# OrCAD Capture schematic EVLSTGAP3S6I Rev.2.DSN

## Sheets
1 Gate Driver: size A3; rev: R2; note: <Doc>
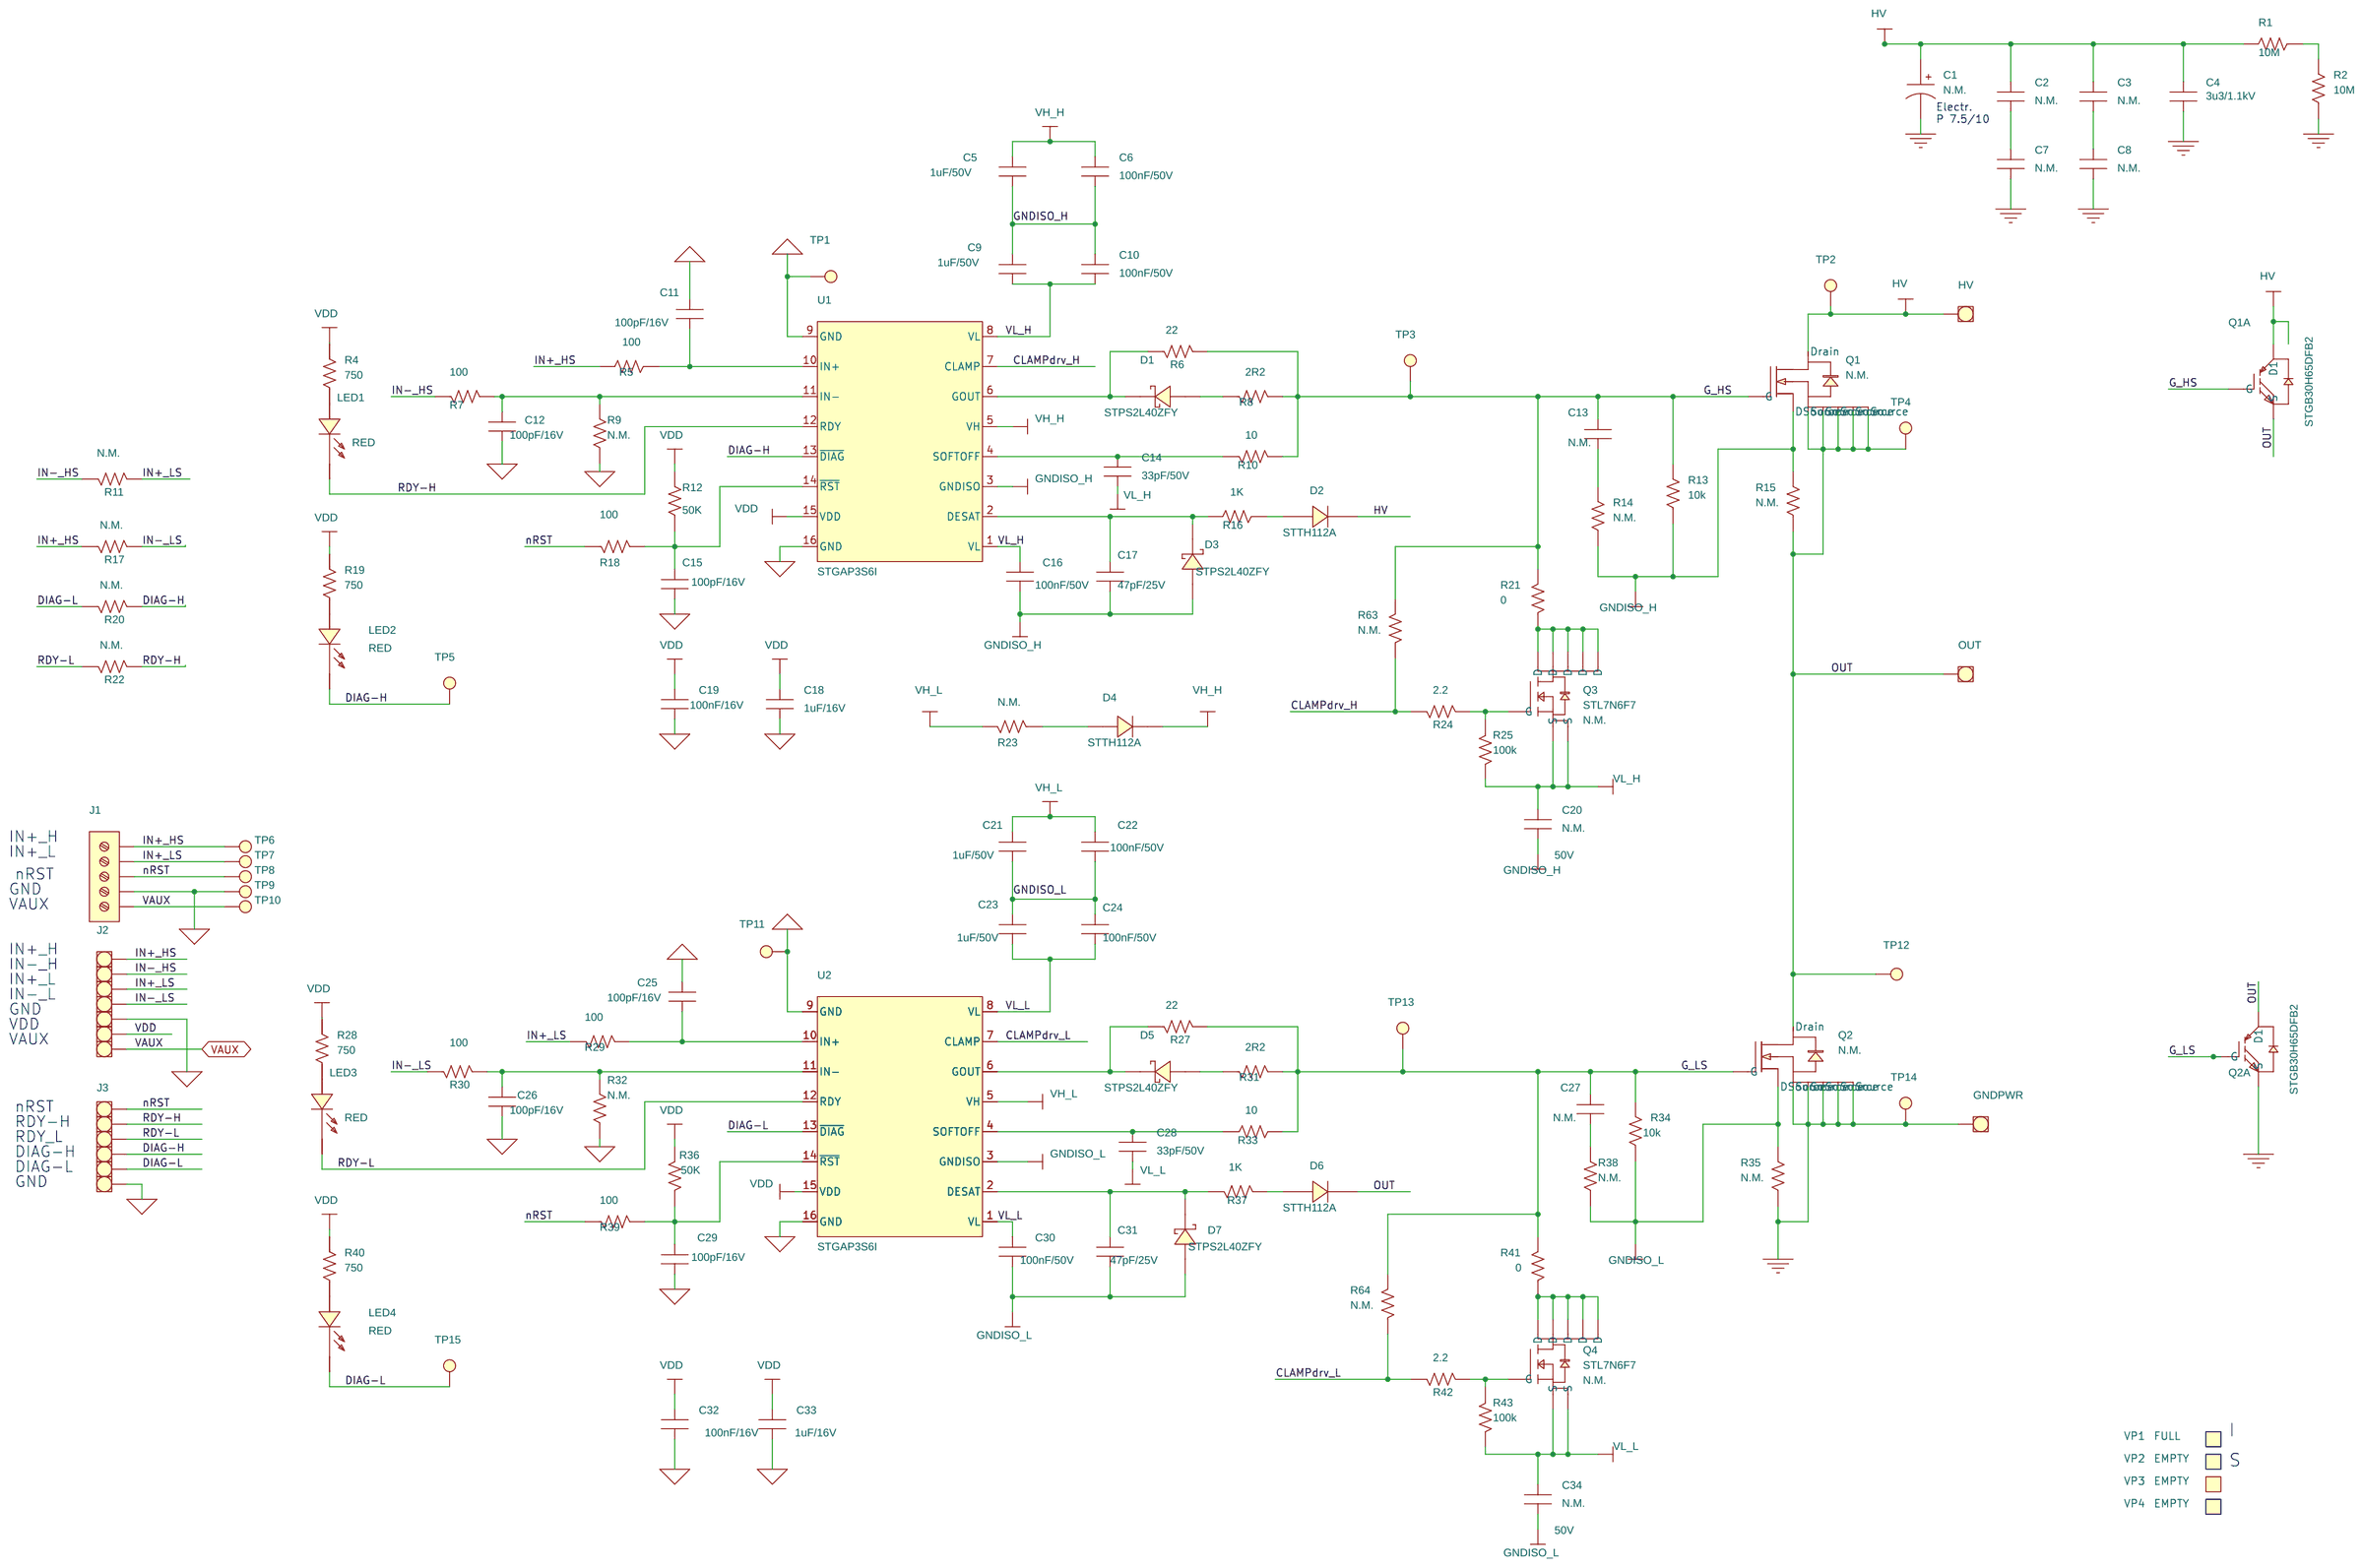
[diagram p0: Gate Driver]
2 Supply: size A4
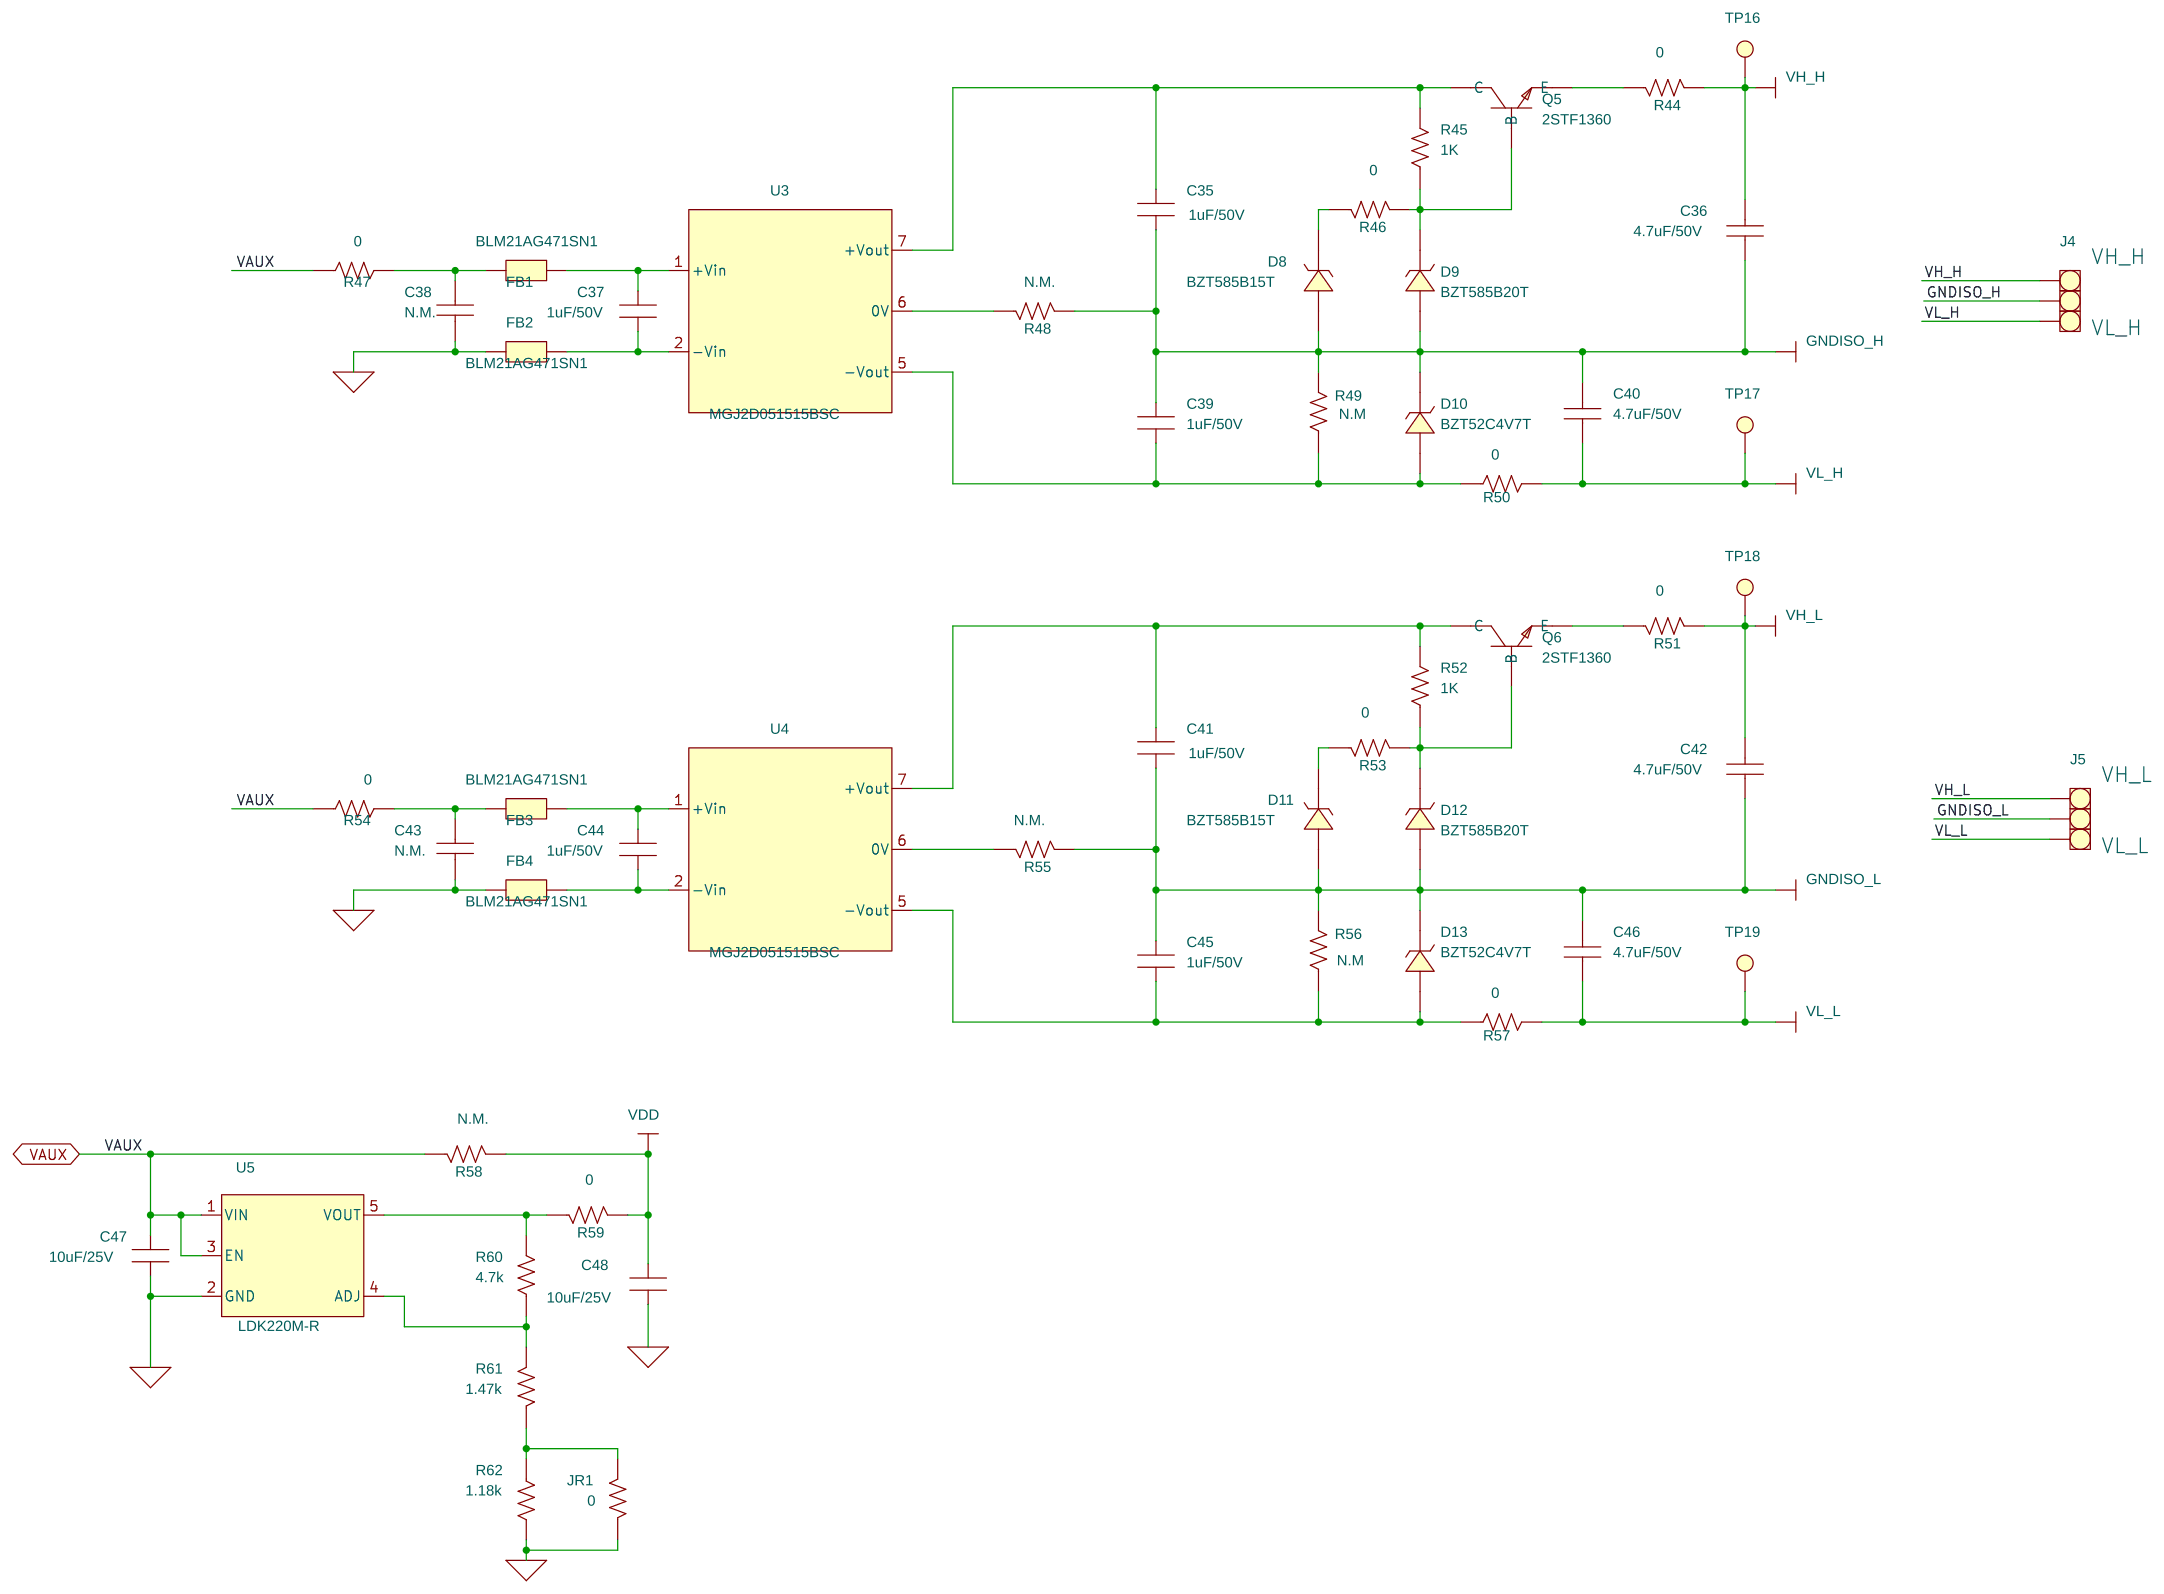
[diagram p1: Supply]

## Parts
sheet Gate Driver
C1  N.M.  [CAPE-R22H50-P100]
C2  N.M.  [C2225]
C3  N.M.  [C2225]
C4  3u3/1.1kV  [CAP-RAD-16X31_5H29_5P27_5]
C5  1uF/50V  [C0603]
C6  100nF/50V  [C0603]
C7  N.M.  [C2225]
C8  N.M.  [C2225]
C9  1uF/50V  [C0603]
C10  100nF/50V  [C0603]
C11  100pF/16V  [C0603]
C12  100pF/16V  [C0603]
C13  N.M.  [C0603]
C14  33pF/50V  [C0402]
C15  100pF/16V  [C0603]
C16  100nF/50V  [C0603]
C17  47pF/25V  [C0603]
C18  1uF/16V  [C0603]
C19  100nF/16V  [C0603]
C20  N.M.  [C0603]
C21  1uF/50V  [C0603]
C22  100nF/50V  [C0603]
C23  1uF/50V  [C0603]
C24  100nF/50V  [C0603]
C25  100pF/16V  [C0603]
C26  100pF/16V  [C0603]
C27  N.M.  [C0603]
C28  33pF/50V  [C0402]
C29  100pF/16V  [C0603]
C30  100nF/50V  [C0603]
C31  47pF/25V  [C0603]
C32  100nF/16V  [C0603]
C33  1uF/16V  [C0603]
C34  N.M.  [C0603]
D1  STPS2L40ZFY  [SOD-123]
D2  STTH112A  [DO-214AC]
D3  STPS2L40ZFY  [SOD-123]
D4  STTH112A  [DO-214AC]
D5  STPS2L40ZFY  [SOD-123]
D6  STTH112A  [DO-214AC]
D7  STPS2L40ZFY  [SOD-123]
GNDPWR  PAD_4_7D2_4MM  [PAD-10F3_2]
HV  PAD_4_7D2_4MM  [PAD-10F3_2]
J1  MORSV-350-5P_screw  [MORS_WR-TBL_691243110005_5P_3V5]
J2  STRIP 1x7  [STRIP_7V]
J3  STRIP 1x6  [STRIP_6V]
LED1  RED  [led-0805]
LED2  RED  [led-0805]
LED3  RED  [led-0805]
LED4  RED  [led-0805]
OUT  PAD_4_7D2_4MM  [PAD-10F3_2]
Q1  N.M.  [H2PAK-7]
Q1A  STGB30H65DFB2  [D2PAK]
Q2  N.M.  [H2PAK-7]
Q2A  STGB30H65DFB2  [D2PAK]
Q3  STL7N6F7  [POWERFLAT6-2X2_P065-E]
Q4  STL7N6F7  [POWERFLAT6-2X2_P065-E]
R1  10M  [R1206]
R2  10M  [R1206]
R4  750  [R0603]
R5  100  [R0603]
R6  22  [R1210]
R7  100  [R0603]
R8  2R2  [R1210]
R9  N.M.  [R0603]
R10  10  [R0805]
R11  N.M.  [R0402]
R12  50K  [R0603]
R13  10k  [R0402]
R14  N.M.  [R0402]
R15  N.M.  [R0402]
R16  1K  [R0603]
R17  N.M.  [R0402]
R18  100  [R0603]
R19  750  [R0603]
R20  N.M.  [R0402]
R21  0  [R0402]
R22  N.M.  [R0402]
R23  N.M.  [R0805]
R24  2.2  [R0402]
R25  100k  [R0402]
R27  22  [R1210]
R28  750  [R0603]
R29  100  [R0603]
R30  100  [R0603]
R31  2R2  [R1210]
R32  N.M.  [R0603]
R33  10  [R0805]
R34  10k  [R0402]
R35  N.M.  [R0402]
R36  50K  [R0603]
R37  1K  [R0603]
R38  N.M.  [R0402]
R39  100  [R0603]
R40  750  [R0603]
R41  0  [R0402]
R42  2.2  [R0402]
R43  100k  [R0402]
R63  N.M.  [R0402]
R64  N.M.  [R0402]
TP1  TP-diam1_27mm-Hole0_8mm  [TP-F0_8_PAD_1_35]
TP2  TP-diam1_27mm-Hole0_8mm  [TP-F0_8_PAD_1_35]
TP3  TP-diam1_27mm-Hole0_8mm  [TP-F0_8_PAD_1_35]
TP4  TP-diam1_27mm-Hole0_8mm  [TP-F0_8_PAD_1_35]
TP5  TP-diam1_27mm-Hole0_8mm  [TP-F0_8_PAD_1_35]
TP6  TP-diam1_27mm-Hole0_8mm  [TP-1_5]
TP7  TP-diam1_27mm-Hole0_8mm  [TP-1_5]
TP8  TP-diam1_27mm-Hole0_8mm  [TP-1_5]
TP9  TP-diam1_27mm-Hole0_8mm  [TP-1_5]
TP10  TP-diam1_27mm-Hole0_8mm  [TP-1_5]
TP11  TP-diam1_27mm-Hole0_8mm  [TP-F0_8_PAD_1_35]
TP12  TP-diam1_27mm-Hole0_8mm  [TP-F0_8_PAD_1_35]
TP13  TP-diam1_27mm-Hole0_8mm  [TP-F0_8_PAD_1_35]
TP14  TP-diam1_27mm-Hole0_8mm  [TP-F0_8_PAD_1_35]
TP15  TP-diam1_27mm-Hole0_8mm  [TP-F0_8_PAD_1_35]
U1  STGAP3S6I  [SO16_L10_4]
U2  STGAP3S6I  [SO16_L10_4]
VP1  FULL  [square2x2mm]
VP2  EMPTY  [square2x2mm]
VP3  EMPTY  [square2x2mm]
VP4  EMPTY  [square2x2mm]
sheet Supply
C35  1uF/50V  [C0603]
C36  4.7uF/50V  [C1206]
C37  1uF/50V  [C0603]
C38  N.M.  [C0603]
C39  1uF/50V  [C0603]
C40  4.7uF/50V  [C1206]
C41  1uF/50V  [C0603]
C42  4.7uF/50V  [C1206]
C43  N.M.  [C0603]
C44  1uF/50V  [C0603]
C45  1uF/50V  [C0603]
C46  4.7uF/50V  [C1206]
C47  10uF/25V  [C0805]
C48  10uF/25V  [C0805]
D8  BZT585B15T  [SOD-523]
D9  BZT585B20T  [SOD-523]
D10  BZT52C4V7T  [SOD-523]
D11  BZT585B15T  [SOD-523]
D12  BZT585B20T  [SOD-523]
D13  BZT52C4V7T  [SOD-523]
FB1  BLM21AG471SN1  [R0805]
FB2  BLM21AG471SN1  [R0805]
FB3  BLM21AG471SN1  [R0805]
FB4  BLM21AG471SN1  [R0805]
J4  STRIP 1x3  [STRIP_3V]
J5  STRIP 1x3  [STRIP_3V]
JR1  0  [R0603]
Q5  2STF1360  [SOT-89]
Q6  2STF1360  [SOT-89]
R44  0  [R0402]
R45  1K  [R0603]
R46  0  [R0402]
R47  0  [R0603]
R48  N.M.  [R0402]
R49  N.M  [R0603]
R50  0  [R0402]
R51  0  [R0402]
R52  1K  [R0603]
R53  0  [R0402]
R54  0  [R0603]
R55  N.M.  [R0402]
R56  N.M  [R0603]
R57  0  [R0402]
R58  N.M.  [R0402]
R59  0  [R0402]
R60  4.7k  [R0603]
R61  1.47k  [R0603]
R62  1.18k  [R0603]
TP16  TP-diam1_27mm-Hole0_8mm  [TP-1_5]
TP17  TP-diam1_27mm-Hole0_8mm  [TP-1_5]
TP18  TP-diam1_27mm-Hole0_8mm  [TP-1_5]
TP19  TP-diam1_27mm-Hole0_8mm  [TP-1_5]
U3  MGJ2D051515BSC  [CONV_MGJ2]
U4  MGJ2D051515BSC  [CONV_MGJ2]
U5  LDK220M-R  [SOT23-5L]

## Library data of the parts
C1 = C_EL-DIAM10: THT Electrolitic capacitor; Package: Radial p7.5/10 d22; VOLTAGE: <VOLTAGE>
C2 C3 C7 C8 = C-2225: VOLTAGE: <VOLTAGE>
C4 = C-pitch15mm-13x18: Film capacitor; Manufacturer: Panasonic; Manufacturer Order code: ECWFG1B335J; Package: Pitch 27.5 mm; Part Number: ECWFG1B335J; VOLTAGE: <VOLTAGE>
C5 C6 C9-C13 C15-C19 C21-C27 C29-C33 = C-0603: VOLTAGE: <VOLTAGE>
C14 C28 = C-0402: VOLTAGE: <VOLTAGE>
C20 C34 = C-0603: Ifarcad Footprint: CAPC-0603; VOLTAGE: 50V
D1 D3 D5 D7 = STPS2L40ZFY_0
D2 D6 = STTH112A_1
D4 = STTH112A_1: Ifarcad Footprint: DIODO-DO214AC-SMA
GNDPWR HV OUT = PAD_4_7D2_4MM: Package: Diam. 10, hole diam. 3.2 mm
J1 = MORSV-350-5P_screw
J2 = STRIP_1x7: Strip connector 7 pos, 2.54 mm; Part Number: 68000-407HLF or Equivalent
J3 = STRIP_1x6
LED1-LED4 = LED-0805-RED-WE
Q1 Q2 = SCTH40N120G2V7AG_1: Silicon carbide Power MOSFET, 1200 V, 60 A, 35 mOhm; Part Number: SCTH60N120G2-7 or equivalent
Q1A Q2A = STGB50H65FB2_1: Trench gate field-stop, 650 V, 30 A, high-speed HB2 series IGBT; Ampere: 30 A
Q3 Q4 = STL7N6F7_0: Voltage: N.M.
R1 R2 = R-1206: SMT Resistor
R4 R5 R7 R9 R12 R16 R18 R19 R28-R30 R32 R36 R37 R39 R40 = R-0603
R6 R8 R27 R31 = R-1210
R10 R33 = R-0805
R11 R13-R15 R17 R34 R35 R38 R44 R46 R48 R50 R51 R53 R55 R57 = R-0402
R20-R22 R24 R25 R41-R43 R58 R59 R63 R64 = R-0402: Ifarcad Footprint: RESC-0402
R23 = R: SMT Resistor; Ifarcad Footprint: RESC-0805; Package: Size 0805
TP1-TP19 = TP-diam1_27mm-Hole0_8mm
U1 = STGAP3S1_6
U2 = STGAP3S1_6: Galvanically isolated 6 A single gate driver
VP1-VP4 = VERSION-POINT: PCB Assembly version solder dot
C35 C37 C39 C41 C44 C45 = C-0603: SMT Ceramic capacitor; VOLTAGE: <VOLTAGE>
C36 C40 C42 C46 = CAPACITOR_NON-POL: SMT Ceramic capacitor; Package: Size 1206
C38 C43 = CAPACITOR_NON-POL: SMT Ceramic capacitor; Package: Size 0603
C47 C48 = C-0805: Ifarcad Footprint: CAPC-0805; VOLTAGE: <VOLTAGE>
D8 D11 = BZT585B15T
D9 D12 = ZENER-SOD523: SURFACE MOUNT PRECISION ZENER DIODE; Manufacturer: Diodes Incorporated; Part Number: BZT585B20T or Equivalent
D10 D13 = BZT52C4V7T
FB1-FB4 = FERRITE-BEADS: Ferrite Beads; Manufacturer: Murata; Package: Size 0805; Part Number: BLM21AG471SN1 or Equivalent
J4 J5 = STRIP_1x3
JR1 = JUMPER-R0603: Ifarcad Footprint: JP2SO-0603
Q5 Q6 = 2STF1360_0: Low voltage fast-switching NPN power transistors; Manufacturer: STMicroelectronics; Part Number: 2STF1360 or Equivalent
R45 R47 R49 R52 R54 R56 = R: SMT Resistor; Package: Size 0603
R60-R62 = R-0603: Ifarcad Footprint: RESC-0603
U3 U4 = MGJ2D051515BSC
U5 = LDK220M-R: Ifarcad Footprint: SOT23-5

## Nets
GND_SIGNAL: C11.1 C12.1 C15.1 C18.1 C19.1 C25.1 C26.1 C29.1 C32.1 C33.1 C38.2 C43.2 C47.1 C48.1 FB2.1 FB4.1 J1.4 J2.5 J3.6 JR1.1 R9.1 R32.1 R62.2 TP1.1 TP9.1 TP11.1 U1.9(GND) U1.16(GND) U2.9(GND) U2.16(GND) U5.2(GND)
GNDISO_H: C5.1 C6.1 C9.2 C10.2 C16.2 C17.1 C20.2 C35.1 C36.1 C39.2 C40.2 D3.2 D8.2(ANODE) D9.2(ANODE) D10.1(CATHODE) J4.2 Q1.2(DSource) R13.1 R14.1 R15.2 R48.2 R49.2 U1.3(GNDISO)
GNDISO_L: C21.1 C22.1 C23.2 C24.2 C30.2 C31.1 C34.2 C41.1 C42.1 C45.2 C46.2 D7.2 D11.2(ANODE) D12.2(ANODE) D13.1(CATHODE) J5.2 Q2.2(DSource) R34.1 R35.2 R38.1 R55.2 R56.2 U2.3(GNDISO)
GNDPWR: C1.2(NEG) C4.1 C7.1 C8.1 GNDPWR.1 Q2.3(Source) Q2.4(Source) Q2.5(Source) Q2.6(Source) Q2.7(Source) Q2A.3(S) R2.1 R35.1 TP14.1
VDD: C18.2 C19.2 C32.2 C33.2 C48.2 J2.6 R4.2 R12.2 R19.2 R28.2 R36.2 R40.2 R58.2 R59.2 U1.15(VDD) U2.15(VDD)
CLAMPdrv_H: R24.1 R63.1 U1.7(CLAMP)
CLAMPdrv_L: R42.1 R64.1 U2.7(CLAMP)
DIAG-H: J3.4 LED2.1 R20.2 TP5.1 U1.13(~{DIAG})
DIAG-L: J3.5 LED4.1 R20.1 TP15.1 U2.13(~{DIAG})
G_HS: C13.2 Q1.1(G) Q1A.1(G) R6.2 R8.2 R10.2 R13.2 R21.2 R63.2 TP3.1
G_LS: C27.2 Q2.1(G) Q2A.1(G) R27.2 R31.2 R33.2 R34.2 R41.2 R64.2 TP13.1
HV: C1.1(POS) C2.2 C3.2 C4.2 D2.1 HV.1 Q1.8(Drain) Q1A.4(D1) R1.2 TP2.1
IN+_HS: J1.1 J2.1 R5.2 R17.1 TP6.1
IN+_LS: J1.2 J2.3 R11.2 R29.1 TP7.1
IN-_HS: J2.2 R7.1 R11.1
IN-_LS: J2.4 R17.2 R30.1
nRST: J1.3 J3.1 R18.1 R39.1 TP8.1
OUT: D6.1 OUT.1 Q1.3(Source) Q1.4(Source) Q1.5(Source) Q1.6(Source) Q1.7(Source) Q1A.3(S) Q2.8(Drain) Q2A.4(D1) R15.1 TP4.1 TP12.1
RDY-H: J3.2 LED1.1 R22.2 U1.12(RDY)
RDY-L: J3.3 LED3.1 R22.1 U2.12(RDY)
VAUX: C47.2 J1.5 J2.7 R47.1 R54.1 R58.1 TP10.1 U5.1(VIN) U5.3(EN)
VH_H: C5.2 C6.2 C36.2 D4.1 J4.3 R44.2 TP16.1 U1.5(VH)
VH_L: C21.2 C22.2 C42.2 J5.3 R23.2 R51.2 TP18.1 U2.5(VH)
VL_H: C9.1 C10.1 C14.1 C16.1 C20.1 C40.1 J4.1 Q3.4(S) Q3.8(S) R25.2 R50.2 TP17.1 U1.1(VL) U1.8(VL)
VL_L: C23.1 C24.1 C28.1 C30.1 C34.1 C46.1 J5.1 Q4.4(S) Q4.8(S) R43.2 R57.2 TP19.1 U2.1(VL) U2.8(VL)
N16435324: C37.1 FB1.2 U3.1(+Vin)
N16435348: C37.2 FB2.2 U3.2(-Vin)
N16435442: C38.1 FB1.1 R47.2
N16436009: D9.1(CATHODE) Q5.1(B) R45.1 R46.2
N16436033: C39.1 D10.2(ANODE) R49.1 R50.1 U3.5(-Vout)
N16436085: D8.1(CATHODE) R46.1
N16436375: C35.2 Q5.2(C) R45.2 U3.7(+Vout)
N16436395: Q5.3(E) R44.1
N16440193: R1.1 R2.2
N16449698: C17.2 D3.1 R16.2 U1.2(DESAT)
N16450369: D1.1 R6.1 U1.6(GOUT)
N16450393: D1.2 R8.1
N16454045: C31.2 D7.1 R37.1 U2.2(DESAT)
N16454073: D6.2 R37.2
N16454215: D5.1 R27.1 U2.6(GOUT)
N16454235: D5.2 R31.1
N16459777: C25.2 R29.2 U2.10(IN+)
N16461917: C15.2 R12.1 R18.2 U1.14(~{RST})
N16462279: C11.2 R5.1 U1.10(IN+)
N16462299: C12.2 R7.2 R9.2 U1.11(IN-)
N16604212: Q4.3(G) R42.2 R43.1
N16606674: Q3.3(G) R24.2 R25.1
N16609193: R59.1 R60.2 U5.5(VOUT)
N16609281: R60.1 R61.2 U5.4(ADJ)
N16609329: JR1.2 R61.1 R62.1
N16617325: D2.2 R16.1
N16620609: C27.1 R38.2
N16623492: C13.1 R14.2
N16630507: D4.2 R23.1
N16636383: C2.1 C7.2
N16636469: C3.1 C8.2
N16647913: C26.2 R30.2 R32.2 U2.11(IN-)
N16647969: C29.2 R36.1 R39.2 U2.14(~{RST})
N16659533: C41.2 Q6.2(C) R52.2 U4.7(+Vout)
N16659557: Q6.3(E) R51.1
N16659577: D12.1(CATHODE) Q6.1(B) R52.1 R53.2
N16659585: D11.1(CATHODE) R53.1
N16659631: C43.1 FB3.1 R54.2
N16659643: C44.1 FB3.2 U4.1(+Vin)
N16659681: C44.2 FB4.2 U4.2(-Vin)
N16659765: C45.1 D13.2(ANODE) R56.1 R57.1 U4.5(-Vout)
N16681015: Q4.1(D) Q4.2(D) Q4.5(D) Q4.6(D) Q4.7(D) R41.1
N16681091: Q3.1(D) Q3.2(D) Q3.5(D) Q3.6(D) Q3.7(D) R21.1
N16706392: C28.2 R33.1 U2.4(SOFTOFF)
N16706479: C14.2 R10.1 U1.4(SOFTOFF)
N16716595: R48.1 U3.6(0V)
N16716713: R55.1 U4.6(0V)
N16798501: LED3.2 R28.1
N16798502: LED1.2 R4.1
N16798503: LED4.2 R40.1
N16798504: LED2.2 R19.1

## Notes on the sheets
sheet 1
- Electr.
  P 7.5/10
- IN+_H
- IN+_L
- nRST
- GND
- VAUX
- IN+_H
- IN-_H
- IN+_L
- GND
- IN-_L
- VDD
- VAUX
- nRST
- RDY-H
- DIAG-H
- RDY_L
- DIAG-L
- GND
- I
- S
sheet 2
- VH_H
- VL_H
- VH_L
- VL_L
